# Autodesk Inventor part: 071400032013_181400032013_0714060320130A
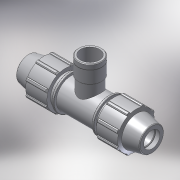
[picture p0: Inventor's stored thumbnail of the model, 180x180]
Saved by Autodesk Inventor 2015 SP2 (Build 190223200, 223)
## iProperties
Created: 2017-02
Part Number: 071400032013_181400032013_0714060320130A
Material: PVC-Piping
Description: PLASSON TEE WITH THREADED FEMALE OFFTAKE 32-1.1/4"-32
Document SubType Name: Modeling
Designer: KIM
Mass: 92.6774 g
Surface Area: 199.44 cm^2
Volume: 66.1981 cm^3
Density: 1.4 g/cm^3
Appearance: Smooth - White
Author: KIM
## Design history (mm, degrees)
derived "07140.ipt"
feature "Solid1::07140.ipt"
feature "Solid2::07140.ipt"
tag "TaggingFeature1"
body "Solid1"
other parameters: "d2" = 32, "d4" = 7.58333, "d5" = 21.84, "d7" = 64, "d11" = 3.03333, "d13" = 120 deg, "d14" = 48, "d15" = 12 deg, "d16" = 55.68, "d18" = 1.6, "d19" = 35 deg, "d20" = 17.5 deg, "d21" = 59.52, "d23" = 0, "d25" = 360 deg, "d27" = 1.28, "d33" = 0.64, "d42" = 32.76, "d43" = 1.92, "d46" = 0.96, "d68" = 5.46, "d72" = 65, "d76" = 38.952, "d80" = 1.16856, "d91" = 48, "d93" = 67, "d95" = 28.8, "d112" = 25, "d115" = 48.69, "d116" = 135 deg, "d117" = 44.7948, "d118" = 182, "d119" = 28.8, "d121" = 0, "d122" = 28.8, "d124" = 0, "d128" = 0, "d129" = 3.2, "d130" = 7.5, "d131" = 0.3, "d132" = 0.3, "d133" = 48.69, "d_" = 32, "E_" = 64, "A_" = 65, "l_" = 67, "l_2" = 25, "Rp_" = 38.952, "H_" = 182
